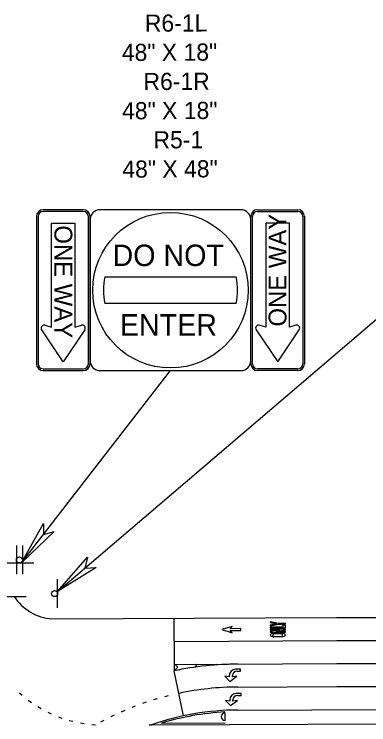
# Model space of a CAD drawing. Extents: x 582908 to 586040, y 1530940 to 1532988.
# Drawn here: x 583736 to 584025, y 1532406 to 1532986 of the extents above; entities that cross this region are included whole.
import ezdxf

# ---------------------------------------------------------------- set-up
doc = ezdxf.new("R2010")
doc.units = 0
for name, color, linetype in [('DirArrowsPavt', 7, 'Continuous'), ('LeaderLine_dp', 7, 'Continuous'), ('PavtMessage', 7, 'Continuous'), ('PMStripe12W', 7, 'Continuous'), ('PMStripe18W', 7, 'Continuous'), ('PMStripe24W', 7, 'Continuous'), ('PMStripe6W', 7, 'Continuous'), ('PMStripe6W(2-4)', 7, 'Continuous'), ('PMStripe6Y', 7, 'Continuous'), ('PMStripe6Y(2-4)', 7, 'Continuous'), ('PMStripe8W', 7, 'Continuous'), ('SignPanel', 7, 'Continuous'), ('SignSupport', 7, 'Continuous'), ('TextLabel', 7, 'Continuous')]:
    doc.layers.add(name, color=color, linetype=linetype)

msp = doc.modelspace()

# ---------------------------------------------------------------- linework, layer by layer
at = {"layer": 'DirArrowsPavt'}
for p, q in [((583913.26, 1532486.2), (583905.07, 1532483.56)), ((583911.71, 1532484.37), (583913.26, 1532486.2)), ((583920.43, 1532484.41), (583911.71, 1532484.37)), ((583920.44, 1532482.85), (583920.43, 1532484.41)), ((583905.07, 1532483.56), (583913.28, 1532480.99)), ((583911.71, 1532482.81), (583920.44, 1532482.85)), ((583913.28, 1532480.99), (583911.71, 1532482.81))]:
    msp.add_line(p, q, dxfattribs=at)
for points in [[(583917.18, 1532449.72), (583920.31, 1532449.72), (583920.31, 1532451.28), (583916.15, 1532451.29)], [(583910.93, 1532446.09), (583910.93, 1532445.05), (583907.41, 1532445.57), (583911.44, 1532441.4)], [(583911.44, 1532441.4), (583917.18, 1532445.56), (583913.53, 1532445.04), (583913.53, 1532446.09)], [(583917.66, 1532429.89), (583920.79, 1532429.88), (583920.79, 1532431.45), (583916.62, 1532431.45)], [(583911.41, 1532426.25), (583911.4, 1532425.21), (583907.89, 1532425.74), (583911.92, 1532421.57)], [(583911.92, 1532421.57), (583917.65, 1532425.72), (583914.01, 1532425.21), (583914.01, 1532426.25)]]:
    msp.add_lwpolyline(points, dxfattribs=at)
for centre, radius in [((583916.14, 1532446.08), 5.21), ((583917.18, 1532446.08), 3.65), ((583916.61, 1532426.24), 5.21), ((583917.66, 1532426.24), 3.65)]:
    msp.add_arc(centre, radius, 89.90326, 179.90326, dxfattribs=at)
at = {"layer": 'LeaderLine_dp'}
for p, q in [((583770.98, 1532514.7), (584096.08, 1532792.5)), ((583741.46, 1532537.97), (583863.01, 1532694.88)), ((583741.46, 1532537.97), (583759.52, 1532570.24)), ((583759.52, 1532570.24), (583759.38, 1532561.1)), ((583768.2, 1532563.52), (583741.46, 1532537.97)), ((583759.38, 1532561.1), (583768.2, 1532563.52)), ((583770.98, 1532514.7), (583795.22, 1532542.63)), ((583795.22, 1532542.63), (583793.22, 1532533.71)), ((583802.35, 1532534.29), (583770.98, 1532514.7)), ((583793.22, 1532533.71), (583802.35, 1532534.29))]:
    msp.add_line(p, q, dxfattribs=at)
at = {"layer": 'PavtMessage'}
for p, q in [((583951.07, 1532488.65), (583944.29, 1532489.92)), ((583944.29, 1532489.92), (583944.3, 1532489.39)), ((583944.3, 1532489.39), (583949.67, 1532488.38)), ((583949.67, 1532488.38), (583944.31, 1532487.33)), ((583944.31, 1532486.8), (583951.07, 1532488.13)), ((583944.31, 1532487.33), (583944.31, 1532486.8)), ((583954.73, 1532485.54), (583944.31, 1532485.49)), ((583944.31, 1532485.49), (583944.32, 1532484.97)), ((583944.32, 1532484.97), (583956.82, 1532485.03)), ((583956.8, 1532488.67), (583951.07, 1532488.65)), ((583951.07, 1532488.13), (583956.8, 1532488.15)), ((583956.81, 1532487.11), (583954.72, 1532487.1)), ((583954.72, 1532487.1), (583954.73, 1532485.54)), ((583956.8, 1532488.15), (583956.8, 1532488.67)), ((583956.82, 1532485.03), (583956.81, 1532487.11)), ((583956.82, 1532483.99), (583944.32, 1532483.93)), ((583944.32, 1532483.93), (583944.32, 1532483.41)), ((583944.32, 1532483.41), (583952.29, 1532483.45)), ((583952.29, 1532483.45), (583944.33, 1532481.98)), ((583944.33, 1532481.98), (583944.33, 1532481.46)), ((583944.33, 1532481.46), (583956.83, 1532481.51)), ((583947.37, 1532480.69), (583953.8, 1532480.72)), ((583953.09, 1532480.19), (583948.09, 1532480.17)), ((583949.02, 1532482), (583956.82, 1532483.47)), ((583956.83, 1532482.03), (583949.02, 1532482)), ((583956.82, 1532483.47), (583956.82, 1532483.99)), ((583956.83, 1532481.51), (583956.83, 1532482.03)), ((583953.82, 1532477.59), (583947.38, 1532477.57)), ((583948.1, 1532478.09), (583953.1, 1532478.11))]:
    msp.add_line(p, q, dxfattribs=at)
for major_axis, ratio, start_param, end_param in [((-6.25, -0.03), 0.291667, 5.253489, 7.312882), ((-4.17, -0.02), 0.3125, 5.35589, 7.210481), ((-4.17, -0.02), 0.3125, 2.214297, 4.068888), ((-6.25, -0.03), 0.291667, 2.111896, 4.171289)]:
    msp.add_ellipse((583950.59, 1532479.14), major_axis=major_axis, ratio=ratio, start_param=start_param, end_param=end_param, dxfattribs=at)
at = {"layer": 'PMStripe12W'}
msp.add_line((583570.9, 1532509.82), (583745.38, 1532510.59), dxfattribs=at)
at = {"layer": 'PMStripe18W'}
for p, q in [((583883.81, 1532455.34), (583884.68, 1532454.47)), ((583900.06, 1532455.42), (583900.31, 1532455.18)), ((583865.99, 1532449.94), (583869.07, 1532453.05)), ((583866.83, 1532455.27), (583869.07, 1532453.05)), ((583883.2, 1532452.98), (583884.68, 1532454.47)), ((583899.92, 1532454.78), (583900.31, 1532455.18))]:
    msp.add_line(p, q, dxfattribs=at)
at = {"layer": 'PMStripe24W'}
for p, q in [((583865.89, 1532492.76), (583866.06, 1532455.26)), ((583873.75, 1532413.26), (583865.99, 1532449.94))]:
    msp.add_line(p, q, dxfattribs=at)
at = {"layer": 'PMStripe6W'}
for p, q in [((583866.32, 1532474.02), (583998.69, 1532474.6)), ((583998.69, 1532474.6), (584188.53, 1532475.44)), ((583866.06, 1532455.26), (583998.77, 1532455.85)), ((583998.77, 1532455.85), (584188.62, 1532456.69)), ((583998.86, 1532437.1), (584764.47, 1532440.5)), ((583917.99, 1532436.74), (583998.86, 1532437.1))]:
    msp.add_line(p, q, dxfattribs=at)
msp.add_arc((583919.04, 1532199.25), 237.5, 90.25398, 101.94955, dxfattribs=at)
at = {"layer": 'PMStripe6W(2-4)'}
for p, q in [((583852.12, 1532427.12), (583849.12, 1532426.22)), ((583861.16, 1532429.59), (583858.14, 1532428.8)), ((583834.35, 1532421.13), (583831.44, 1532420)), ((583843.18, 1532424.3), (583840.22, 1532423.29)), ((583825.66, 1532417.62), (583822.8, 1532416.37)), ((583808.73, 1532409.58), (583805.97, 1532408.11)), ((583817.12, 1532413.76), (583814.3, 1532412.4))]:
    msp.add_line(p, q, dxfattribs=at)
at = {"layer": 'PMStripe6Y'}
for p, q in [((583918.07, 1532417.99), (584815.89, 1532421.97)), ((583907.57, 1532409.35), (583907.54, 1532415.6)), ((583847.49, 1532405.96), (584975.54, 1532410.96)), ((583855.82, 1532407.3), (583907.58, 1532407.53))]:
    msp.add_line(p, q, dxfattribs=at)
for centre, radius, start, end in [((583919.04, 1532199.25), 218.75, 90.25398, 109.09317), ((583919.04, 1532199.25), 217.45, 93.04198, 106.90179), ((583907.56, 1532412.48), 3.12, 90.25398, 270.25398)]:
    msp.add_arc(centre, radius, start, end, dxfattribs=at)
at = {"layer": 'PMStripe6Y(2-4)'}
for p, q in [((583739.77, 1532432.05), (583742.12, 1532429.99)), ((583747, 1532426.09), (583749.53, 1532424.25)), ((583754.75, 1532420.82), (583757.44, 1532419.22)), ((583762.95, 1532416.29), (583765.77, 1532414.95)), ((583771.54, 1532412.53), (583774.47, 1532411.45)), ((583780.43, 1532409.58), (583783.45, 1532408.78)), ((583789.56, 1532407.46), (583792.64, 1532406.94)), ((583798.85, 1532406.19), (583801.96, 1532405.96)), ((583845.71, 1532405.96), (583847.49, 1532405.96))]:
    msp.add_line(p, q, dxfattribs=at)
at = {"layer": 'PMStripe8W'}
for p, q in [((583998.61, 1532493.35), (584975.15, 1532497.68)), ((583766.26, 1532492.32), (583998.61, 1532493.35)), ((583866.06, 1532455.26), (583865.99, 1532449.94))]:
    msp.add_line(p, q, dxfattribs=at)
for centre, radius, start, end in [((583769.45, 1532532.69), 40.5, 213.15386, 265.48722), ((583919.04, 1532199.25), 256.25, 90.25398, 101.94955)]:
    msp.add_arc(centre, radius, start, end, dxfattribs=at)
at = {"layer": 'SignPanel'}
for p, q in [((583753.64, 1532820.66), (583753.64, 1532700.35)), ((583755, 1532820.66), (583755, 1532700.35)), ((583791.92, 1532826.13), (583759.1, 1532826.13)), ((583791.92, 1532824.76), (583759.1, 1532824.76)), ((583796.02, 1532700.35), (583796.02, 1532820.66)), ((583797.39, 1532700.35), (583797.39, 1532820.66)), ((583920.43, 1532826.13), (583805.59, 1532826.13)), ((583928.64, 1532700.35), (583928.64, 1532820.66)), ((583930, 1532700.35), (583930, 1532820.66)), ((583934.1, 1532826.13), (583966.92, 1532826.13)), ((583934.1, 1532824.76), (583966.92, 1532824.76)), ((583971.02, 1532820.66), (583971.02, 1532700.35)), ((583972.39, 1532820.66), (583972.39, 1532700.35)), ((583765.94, 1532730.43), (583765.94, 1532815.19)), ((583765.94, 1532815.19), (583785.08, 1532815.19)), ((583785.08, 1532815.19), (583785.08, 1532730.43)), ((583797.39, 1532817.93), (583797.39, 1532703.08)), ((583928.64, 1532703.08), (583928.64, 1532817.93)), ((583960.08, 1532815.19), (583940.94, 1532815.19)), ((583940.94, 1532815.19), (583940.94, 1532730.43)), ((583960.08, 1532730.43), (583960.08, 1532815.19)), ((583809.43, 1532771.44), (583916.59, 1532771.44)), ((583916.59, 1532749.57), (583809.43, 1532749.57)), ((583775.51, 1532702.17), (583757.94, 1532728.11)), ((583760.71, 1532731.93), (583765.94, 1532730.43)), ((583793.08, 1532728.11), (583775.51, 1532702.17)), ((583785.08, 1532730.43), (583790.32, 1532731.93)), ((583932.94, 1532728.11), (583950.51, 1532702.17)), ((583940.94, 1532730.43), (583935.7, 1532731.93)), ((583950.51, 1532702.17), (583968.08, 1532728.11)), ((583965.32, 1532731.93), (583960.08, 1532730.43)), ((583759.1, 1532696.25), (583791.92, 1532696.25)), ((583759.1, 1532694.88), (583791.92, 1532694.88)), ((583805.59, 1532694.88), (583920.43, 1532694.88)), ((583966.92, 1532696.25), (583934.1, 1532696.25)), ((583966.92, 1532694.88), (583934.1, 1532694.88))]:
    msp.add_line(p, q, dxfattribs=at)
msp.add_circle((583863.01, 1532760.5), 63.44, dxfattribs=at)
for centre, radius, start, end in [((583759.1, 1532820.66), 5.47, 90, 180), ((583759.1, 1532820.66), 4.1, 90, 180), ((583791.92, 1532820.66), 5.47, 360, 90), ((583791.92, 1532820.66), 4.1, 360, 90), ((583805.59, 1532817.93), 8.2, 90, 180), ((583920.43, 1532817.93), 8.2, 360, 90), ((583934.1, 1532820.66), 5.47, 90, 180), ((583934.1, 1532820.66), 4.1, 90, 180), ((583966.92, 1532820.66), 5.47, 360, 90), ((583966.92, 1532820.66), 4.1, 360, 90), ((583863.01, 1532760.5), 54.69, 168.46307, 191.53692), ((583863.01, 1532760.5), 54.69, 348.46307, 11.53692), ((583760.02, 1532729.52), 2.51, 74.04541, 214.13318), ((583791.01, 1532729.52), 2.51, 325.88703, 105.93889), ((583935.02, 1532729.52), 2.51, 74.06111, 214.11297), ((583966.01, 1532729.52), 2.51, 325.86682, 105.95459), ((583759.1, 1532700.35), 5.47, 180, 270), ((583759.1, 1532700.35), 4.1, 180, 270), ((583791.92, 1532700.35), 5.47, 270, 360), ((583791.92, 1532700.35), 4.1, 270, 360), ((583805.59, 1532703.08), 8.2, 180, 270), ((583920.43, 1532703.08), 8.2, 270, 360), ((583934.1, 1532700.35), 5.47, 180, 270), ((583934.1, 1532700.35), 4.1, 180, 270), ((583966.92, 1532700.35), 4.1, 270, 360), ((583966.92, 1532700.35), 5.47, 270, 360)]:
    msp.add_arc(centre, radius, start, end, dxfattribs=at)
at = {"layer": 'SignSupport'}
for p, q in [((583737.31, 1532552.1), (583737.31, 1532528.82)), ((583742.29, 1532552.1), (583742.29, 1532528.82)), ((583728.16, 1532537.97), (583751.44, 1532537.97)), ((583770.98, 1532501.4), (583770.98, 1532524.68))]:
    msp.add_line(p, q, dxfattribs=at)
for centre in [(583739.8, 1532540.46), (583768.48, 1532513.04)]:
    msp.add_circle(centre, 2.49, dxfattribs=at)

# ---------------------------------------------------------------- texts
at = {"layer": 'SignPanel'}
for s, height, rotation, p in [('ONE WAY', 14.567, 90, (583957.69, 1532730.84)), ('ONE WAY', 14.567, 270, (583768.34, 1532813.4)), ('DO NOT', 17.482, 360, (583815.76, 1532780.19)), ('ENTER', 17.482, 360, (583821.73, 1532723.49))]:
    msp.add_text(s, height=height, rotation=rotation, dxfattribs=at).set_placement(p)
at = {"layer": 'TextLabel'}
for s, p in [('R6-1L', (583842.14, 1532971.34)), ('48" X 18"', (583823.36, 1532947.46)), ('R6-1R', (583841.02, 1532923.74)), ('48" X 18"', (583823.57, 1532899.86)), ('R5-1', (583849.18, 1532876.17)), ('48" X 48"', (583823.78, 1532852.26))]:
    msp.add_text(s, height=14, rotation=0.25398, dxfattribs=at).set_placement(p)

doc.saveas('drawing.dxf')
